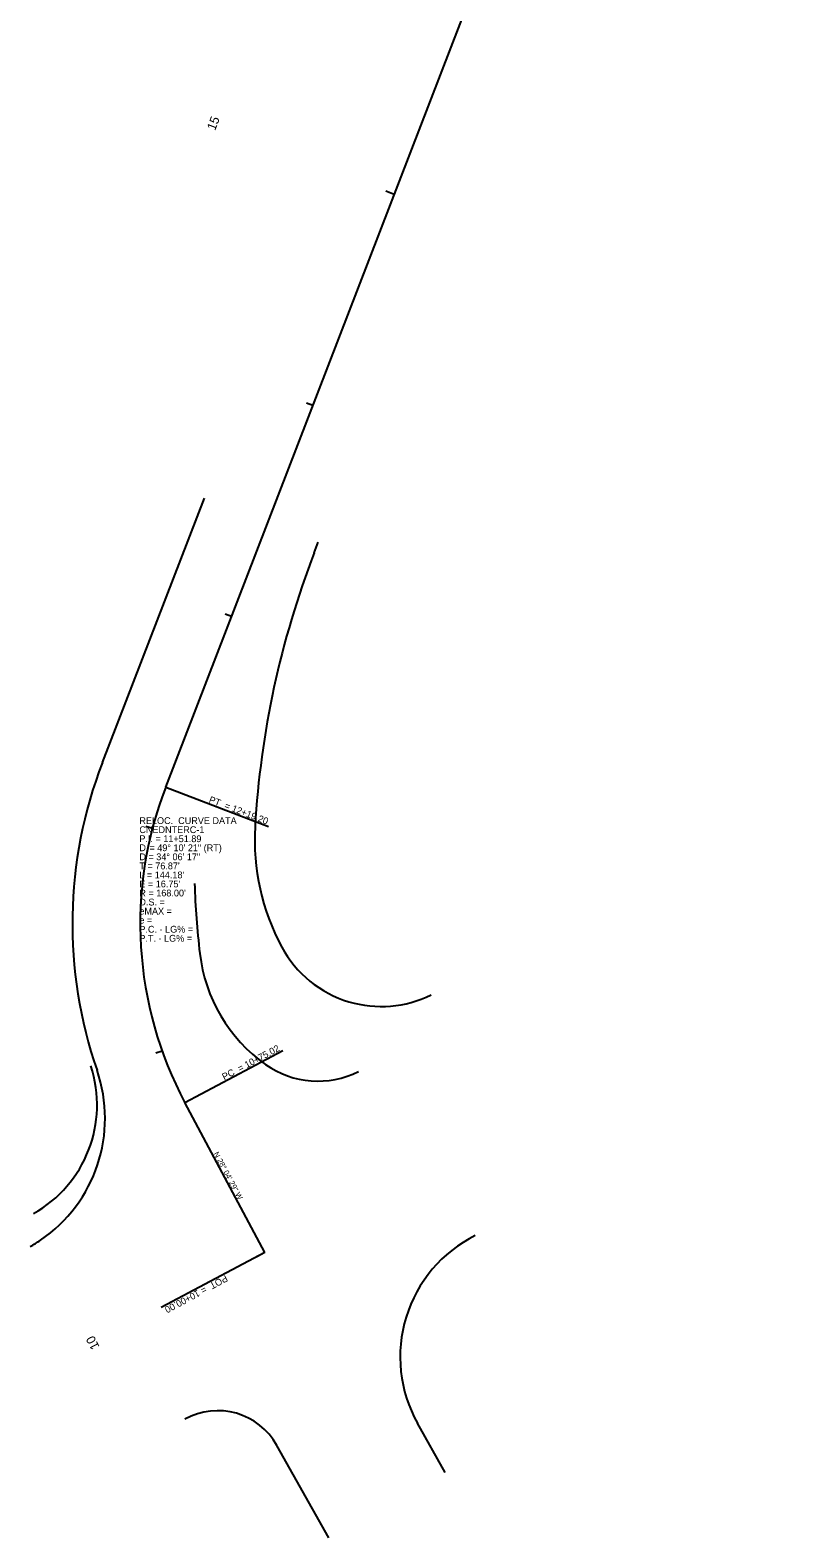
# Model space of a CAD drawing. Extents: x 2004693 to 2005101, y 1136556 to 1137889.
# Drawn here: x 2004693 to 2005032, y 1136556 to 1137223 of the extents above; entities that cross this region are included whole.
import ezdxf

# ---------------------------------------------------------------- set-up
doc = ezdxf.new("R2010")
doc.units = 0
for name, color, linetype in [('RD_HC_CL_Rel', 7, 'Continuous'), ('RD_HC_Data_Rel', 7, 'Continuous'), ('RD_HC_Data_Tic_Rel', 7, 'Continuous'), ('RD_HC_TX_Rel_Sta20', 7, 'Continuous'), ('RD_PD_ConcMed', 7, 'Continuous'), ('RD_PD_Final_TrvlWay', 7, 'Continuous'), ('RD_PD_SW', 7, 'Continuous')]:
    doc.layers.add(name, color=color, linetype=linetype)

msp = doc.modelspace()

# ---------------------------------------------------------------- linework, layer by layer
at = {"layer": 'RD_HC_CL_Rel'}
for p, q in [((2004752.64, 1136888.36), (2005031.77, 1137611.81)), ((2004796.46, 1136682.63), (2004761.15, 1136748.83))]:
    msp.add_line(p, q, dxfattribs=at)
msp.add_arc((2004909.38, 1136827.89), 168, 158.90217, 208.0747, dxfattribs=at)
at = {"layer": 'RD_HC_Data_Rel'}
for p, q in [((2004752.64, 1136888.36), (2004798.04, 1136870.85)), ((2004761.15, 1136748.83), (2004804.46, 1136771.93)), ((2004796.46, 1136682.63), (2004750.71, 1136658.23))]:
    msp.add_line(p, q, dxfattribs=at)
at = {"layer": 'RD_HC_Data_Tic_Rel'}
for p, q in [((2004853.72, 1137150.34), (2004849.99, 1137151.78)), ((2004817.72, 1137057.04), (2004814.92, 1137058.12)), ((2004781.73, 1136963.75), (2004778.93, 1136964.83)), ((2004746.77, 1136870.09), (2004743.87, 1136870.85)), ((2004751.07, 1136771.66), (2004748.25, 1136770.65)), ((2004796.46, 1136682.63), (2004792.93, 1136680.75))]:
    msp.add_line(p, q, dxfattribs=at)
at = {"layer": 'RD_PD_ConcMed'}
for centre, radius, start, end in [((2005165.1, 1136860.63), 400, 182.14127, 186.57433), ((2004837.27, 1136822.84), 70, 186.57433, 234.69632), ((2004819.93, 1136798.36), 40, 234.69583, 296.78201)]:
    msp.add_arc(centre, radius, start, end, dxfattribs=at)
at = {"layer": 'RD_PD_Final_TrvlWay'}
for p, q in [((2004724.65, 1136899.16), (2004769.75, 1137016.05)), ((2004818.33, 1136991.94), (2004820.13, 1136996.61)), ((2004876.2, 1136585.28), (2004863.98, 1136607.09)), ((2004824.72, 1136556.45), (2004801.84, 1136597.3))]:
    msp.add_line(p, q, dxfattribs=at)
for centre, radius, start, end in [((2005191.52, 1136847.96), 400, 158.90217, 176.72819), ((2004909.38, 1136827.89), 198, 158.90217, 199.08936), ((2004892.01, 1136865.08), 100, 176.72819, 208.32727), ((2004847.99, 1136841.35), 50, 208.32727, 253.37153), ((2004847.99, 1136841.35), 50, 253.37153, 296.10396), ((2004660.84, 1136741.88), 65, 304.05538, 19.08936), ((2004660.84, 1136741.88), 65, 299.33961, 304.05538), ((2004916.34, 1136636.4), 60, 116.57024, 209.2438), ((2004775.67, 1136582.65), 30, 29.2438, 118.98413)]:
    msp.add_arc(centre, radius, start, end, dxfattribs=at)
at = {"layer": 'RD_PD_SW'}
msp.add_arc((2004667.29, 1136747.79), 55, 299.2097, 18.30886, dxfattribs=at)

# ---------------------------------------------------------------- texts
at = {"layer": 'RD_HC_Data_Rel'}
for s, height, rotation, p in [('PT  = 12+19.20', 3, 338.90217, (2004771.48, 1136881.63)), ('PC  = 10+75.02', 3, 28.0747, (2004778.56, 1136758.68)), ('N 28%%d 04\' 29" W', 2.4, 298.0747, (2004773.72, 1136726.31)), ('POT  = 10+00.00', 3, 208.0747, (2004779.04, 1136672.78))]:
    msp.add_text(s, height=height, rotation=rotation, dxfattribs=at).set_placement(p)
for s, p in [('RELOC.  CURVE DATA', (2004741, 1136872)), ('CNEDNTERC-1', (2004741, 1136868)), ('P.I. = 11+51.89', (2004741, 1136864)), ('D', (2004741, 1136860)), ('    = 49%%d 10\' 21" (RT)', (2004741, 1136860)), ("T = 76.87'", (2004741, 1136852)), ('D = 34%%d 06\' 17"', (2004741, 1136856)), ("L = 144.18'", (2004741, 1136848)), ("E = 16.75'", (2004741, 1136844)), ("R = 168.00'", (2004741, 1136840)), ('eMAX = ', (2004741, 1136832)), ('D.S. = ', (2004741, 1136836)), ('e = ', (2004741, 1136828)), ('P.C. - LG% =', (2004741, 1136824)), ('P.T. - LG% =', (2004741, 1136820))]:
    msp.add_text(s, height=3, dxfattribs=at).set_placement(p)
at = {"layer": 'RD_HC_TX_Rel_Sta20'}
for s, rotation, p in [('15', 68.90217, (2004774.47, 1137178.3)), ('10', 118.0747, (2004723.49, 1136640.94))]:
    msp.add_text(s, height=4, rotation=rotation, dxfattribs=at).set_placement(p)

doc.saveas('drawing.dxf')
